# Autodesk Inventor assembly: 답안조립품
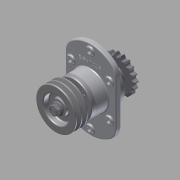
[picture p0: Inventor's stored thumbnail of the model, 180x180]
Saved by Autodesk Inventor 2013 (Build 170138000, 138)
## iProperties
Created: 2015-02
Part Number: 답안조립품
Document SubType Name: Assembly
Designer: kb543-17
Author: kb543-17
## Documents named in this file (12)
- C:\Users\kb543-17\Desktop\450207V1026\답안조립품.iam
- C:\Users\kb543-17\Desktop\450207V1026\1-본체.ipt
- C:\Users\kb543-17\Desktop\450207V1026\6-베어링 6206.ipt
- C:\Users\kb543-17\Desktop\450207V1026\3-축.ipt
- C:\Users\kb543-17\Desktop\450207V1026\7-부시.ipt
- C:\Users\kb543-17\Desktop\450207V1026\2-커버.ipt
- C:\Users\kb543-17\Desktop\450207V1026\8-오일실 30x42.ipt
- C:\Users\kb543-17\Desktop\450207V1026\11-키 6x6.ipt
- C:\Users\kb543-17\Desktop\450207V1026\10-M6.ipt
- C:\Users\kb543-17\Desktop\450207V1026\9-M16-너트.ipt
- C:\Users\kb543-17\Desktop\450207V1026\4-V벨트풀리.ipt
- C:\Users\kb543-17\Desktop\450207V1026\5-체인 스프로킷.ipt
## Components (23 placed, 11 different names)
1. 1-본체:1
2. 6-베어링 6206:1
3. 6-베어링 6206:2
4. 3-축:1 — 각도:1, 각도:2, 각도:5, 각도:6
5. 7-부시:1
6. 2-커버:1
7. 2-커버:2
8. 8-8-오일실 30x42:1
9. 8-8-오일실 30x42:2
10. 11-키 6x6:1 — 각도:1, 각도:3
11. 11-키 6x6:2 — 각도:2, 각도:4
12. 9-M16 너트:1 — 각도:5
13. 9-M16 너트:2 — 각도:6
14. 4-V벨트풀리:1 — 각도:3
15. 5-체인 스프로킷:1 — 각도:4
16. 10-M6:1
17. 10-M6:3
18. 10-M6:4
19. 10-M6:5
20. 10-M6:2
21. 10-M6:6
22. 10-M6:7
23. 10-M6:8
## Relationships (6: Angle 6)
- 각도:1 [Angle]: 3-축:1 ↔ 11-키 6x6:1
- 각도:2 [Angle]: 3-축:1 ↔ 11-키 6x6:2
- 각도:3 [Angle]: 11-키 6x6:1 ↔ 4-V벨트풀리:1
- 각도:4 [Angle]: 11-키 6x6:2 ↔ 5-체인 스프로킷:1
- 각도:5 [Angle]: 3-축:1 ↔ 9-M16 너트:1
- 각도:6 [Angle]: 3-축:1 ↔ 9-M16 너트:2
